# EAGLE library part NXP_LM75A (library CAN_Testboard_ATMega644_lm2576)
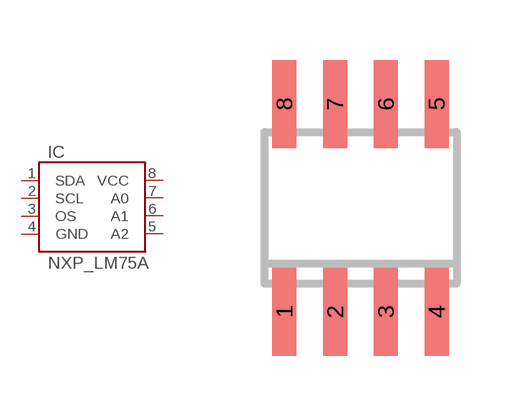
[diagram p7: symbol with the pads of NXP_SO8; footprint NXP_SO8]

Designator prefix IC

## NXP_LM75A  [NXP_SO8]
1  SDA
2  SCL
3  OS
4  GND
5  A2
6  A1
7  A0
8  VCC

## Footprint NXP_SO8 (pad centres in mm)
smd 0.6 x 2.2: 1 -1.905,-2.6; 2 -0.635,-2.6; 3 0.635,-2.6; 4 1.905,-2.6; 5 1.905,2.6; 6 0.635,2.6; 7 -0.635,2.6; 8 -1.905,2.6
